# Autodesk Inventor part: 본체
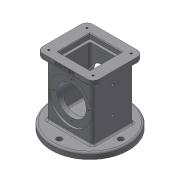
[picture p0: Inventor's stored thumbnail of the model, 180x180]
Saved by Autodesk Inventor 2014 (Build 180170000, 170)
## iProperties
Created: 2018-10
Part Number: 본체
Material: 일반
Document SubType Name: Modeling
Designer: 602-14
Density: 1 g/cm^3
Appearance: 기본값
Author: 602-14
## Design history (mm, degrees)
sketch "스케치1"
  geometry: C1 r 62.5 at (0, 0); 1 further point
  constraints: 1 centre point, 1 coincident
  dimensions: "d0" = 125 diameter of C1
extrude "돌출1" new body sketch "스케치1" distance "d1" = 10; taper "d2" = 0 deg
sketch "스케치2"
  geometry: L1 (37, -33)-(-37, -33); L2 (-37, -33)-(-37, 33); L3 (-37, 33)-(37, 33); L4 (37, 33)-(37, -33); L5 (37, -33)-(-37, 33); L6 (-37, -33)-(37, 33); 1 further point
  constraints: 12 end point, 2 midpoint, 2 parallel, 1 horizontal, 1 perpendicular
  dimensions: "d3" = 74 distance of L2.end L3.end; "d4" = 66 distance of L3.end L1.start
extrude "돌출2" join sketch "스케치2" distance "d5" = 88; taper "d6" = 0 deg
sketch "스케치3"
  geometry: L1 (46, -41)-(-46, -41); L2 (-46, -41)-(-46, 41); L3 (-46, 41)-(46, 41); L4 (46, 41)-(46, -41); L5 (46, -41)-(-46, 41); L6 (-46, -41)-(46, 41); 1 further point
  constraints: 12 end point, 2 midpoint, 2 parallel, 1 horizontal, 1 perpendicular
  dimensions: "d7" = 92 distance of L2.end L3.end; "d8" = 82 distance of L3.end L1.start
extrude "돌출3" join sketch "스케치3" distance "d9" = 10; taper "d10" = 0 deg
sketch "스케치4"
  geometry: L1 (26, -26)-(-26, -26); L2 (-26, -26)-(-26, 26); L3 (-26, 26)-(26, 26); L4 (26, 26)-(26, -26); L5 (26, -26)-(-26, 26); L6 (-26, -26)-(26, 26); 1 further point
  constraints: 12 end point, 2 midpoint, 2 parallel, 1 horizontal, 1 perpendicular
  dimensions: "d11" = 52 distance of L2.end L3.end; "d12" = 52 distance of L3.end L1.start
extrude "돌출4" cut sketch "스케치4" distance "d13" = 8; taper "d14" = 0 deg
sketch "스케치5"
  geometry: L1 (22, -22)-(-22, -22); L2 (-22, -22)-(-22, 22); L3 (-22, 22)-(22, 22); L4 (22, 22)-(22, -22); L5 (22, -22)-(-22, 22); L6 (-22, -22)-(22, 22); 1 further point
  constraints: 12 end point, 2 midpoint, 2 parallel, 1 horizontal, 1 perpendicular
  dimensions: "d15" = 44 distance of L2.end L3.end; "d16" = 44 distance of L3.end L1.start
extrude "돌출5" cut sketch "스케치5" distance "d17" = 74; taper "d18" = 0 deg
sketch "스케치6" dims "d19" = 100
  geometry: 6 further points
  constraints: 2 vertical alignment, 1 coincident, 7 other
  dimensions: "d22" = 360 deg dimension on point (0, 0) point (0, 50) (derived)
hole "구멍1" sketch "스케치6" at (0, 50), (-50, 0), (0, -50), (50, 0) diameter "d24" = 9; stored, may be unused: countersink angle "d28" = 90 deg, drill point angle "d30" = 118 deg; dims "d25" = 6, "d26" = 4, "d27" = 2, "d29" = 8
sketch "스케치7"
  geometry: L1 (98, 33)-(98, 41) reference; L2 (98, 41)-(108, 41) reference; L3 (108, 41)-(108, 26) reference; L4 (108, 26)-(100, 26) reference; L5 (100, 26)-(100, 22) reference; L6 (100, 22)-(26, 22) reference; L7 (26, 22)-(26, -22) reference; L8 (26, -22)-(100, -22) reference; L9 (100, -22)-(100, -26) reference; L10 (100, -26)-(108, -26) reference; L11 (108, -26)-(108, -41) reference; L12 (108, -41)-(98, -41) reference; L13 (98, -41)-(98, -33) reference; L14 (98, -33)-(10, -33) reference; L15 (10, -33)-(10, -45.5) reference; L16 (10, -45.5)-(0, -45.5) reference; L17 (0, -45.5)-(0, 45.5) reference; L18 (0, 45.5)-(10, 45.5) reference; L19 (10, 45.5)-(10, 33) reference; L20 (10, 33)-(98, 33) reference; L21 (10, -62.5)-(0, -62.5) reference; L22 (0, -62.5)-(0, -54.5) reference; L23 (0, -54.5)-(10, -54.5) reference; L24 (10, -54.5)-(10, -62.5) reference; L25 (0, 62.5)-(10, 62.5) reference; L26 (10, 62.5)-(10, 54.5) reference; L27 (10, 54.5)-(0, 54.5) reference; L28 (0, 54.5)-(0, 62.5) reference; L29 (89, -33)-(54, -33); L30 (54, -33)-(54, -30); L31 (54, -30)-(89, -30); L32 (89, -30)-(89, -33); L33 (54, -30)-(78, -30); L34 (78, -30)-(78, 30); L35 (78, 30)-(54, 30); L36 (54, 30)-(54, -30); L37 (54, 30)-(89, 30); L38 (89, 30)-(89, 33); L39 (89, 33)-(54, 33); L40 (54, 33)-(54, 30); 1 further point
  constraints: 24 end point, 6 parallel, 3 horizontal, 3 perpendicular, 2 point on line
  dimensions: "d31" = 54 distance from line of L17 L39.end; "d32" = 48 diameter of L34 L36; "d33" = 70 diameter of L32 L30; "d34" = 70 diameter of L38 L40; "d35" = 3 distance of L37.end L38.end; "d36" = 3 distance of L31.end L29.start; "d37" = 8 distance between parallel lines of L8 L33 (derived)
revolve "회전1" sketch "스케치7" stored, may be unused: angle "d38" = 90 deg
sketch "스케치8"
  geometry: L1 (0, 0)-(18, 0); L2 (18, 0)-(18, -28); L3 (18, -28)-(0, -28); L4 (0, -28)-(0, 0); L5 (0, -28)-(18, -24.826)
  constraints: 10 end point, 2 parallel, 1 horizontal, 1 perpendicular, 1 point on line
  dimensions: "d39" = 18 distance of L1.start L1.end; "d40" = 80 deg angle of L4 L5; "d41" = 56 diameter of L3.end L1
revolve "회전2" sketch "스케치8" stored, may be unused: angle "d42" = 90 deg
sketch "스케치9" dims "d43" = 58
  geometry: L1 (-54.829, -54)-(-54.829, -44) reference; L2 (-54.829, -44)-(-37, -44) reference; L3 (-37, -44)-(-37, 44) reference; L4 (-37, 44)-(-46, 44) reference; L5 (-46, 44)-(-46, 54) reference; L6 (-46, 54)-(46, 54) reference; L7 (46, 54)-(46, 44) reference; L8 (46, 44)-(37, 44) reference; L9 (37, 44)-(37, -44) reference; L10 (37, -44)-(54.829, -44) reference; L11 (54.829, -44)-(54.829, -54) reference; L12 (54.829, -54)-(-54.829, -54) reference; C1 r 24 at (0, 0) reference; C2 r 35 at (0, 0) reference; 6 further points
  constraints: 2 vertical alignment, 1 coincident, 7 other
  dimensions: "d46" = 360 deg dimension on C1.centre point (0, 29) (derived)
hole "구멍2" sketch "스케치9" at (0, 29), (-29, 0), (0, -29), (29, 0) diameter "d48" = 3.242; stored, may be unused: countersink angle "d52" = 90 deg, drill point angle "d54" = 120 deg; dims "d49" = 4, "d50" = 4, "d51" = 2, "d53" = 6
sketch "스케치10"
  geometry: L1 (36, -31)-(-36, -31); L2 (-36, -31)-(-36, 31); L3 (-36, 31)-(36, 31); L4 (36, 31)-(36, -31); L5 (36, -31)-(-36, 31); L6 (-36, -31)-(36, 31); 1 further point
  constraints: 12 end point, 2 midpoint, 2 parallel, 1 horizontal, 1 perpendicular
  dimensions: "d55" = 72 distance of L2.end L3.end; "d56" = 62 distance of L1.end L2.end
hole "구멍3" sketch "스케치10" at (36, 31), (36, -31), (-36, 31), (-36, -31) diameter "d57" = 3.242; stored, may be unused: countersink angle "d61" = 90 deg, drill point angle "d63" = 120 deg; dims "d58" = 4, "d59" = 4, "d60" = 2, "d62" = 6
sketch "스케치11"
  geometry: L1 (83.371, 0)-(83.371, -10) reference; L2 (83.371, -10)-(-17.371, -10) reference; L3 (-17.371, -10)-(-17.371, 0) reference; L4 (-17.371, 0)-(0, 0) reference; L5 (0, 0)-(66, 0) reference; L6 (66, 0)-(83.371, 0) reference; L7 (0, 0)-(0, 88) reference; L8 (0, 88)-(-8, 88) reference; L9 (-8, 88)-(-8, 98) reference; L10 (-8, 98)-(0.724, 98) reference; L11 (0.724, 98)-(0.724, 92) reference; L12 (3.276, 92)-(3.276, 98) reference; L13 (3.276, 98)-(62.724, 98) reference; L14 (62.724, 98)-(62.724, 92) reference; L15 (65.276, 92)-(65.276, 98) reference; L16 (65.276, 98)-(74, 98) reference; L17 (74, 98)-(74, 88) reference; L18 (74, 88)-(66, 88) reference; L19 (66, 88)-(0, 88) reference; L20 (66, 88)-(66, 0) reference; L21 (33, 98)-(33, -10); 2 further points
  constraints: 2 end point, 2 horizontal alignment, 2 point on line, 1 midpoint, 1 parallel
  dimensions: "d64" = 37 distance from line of L2 point (33, 27); "d65" = 43 distance of point (33, 27) point (33, 70)
hole "구멍4" sketch "스케치11" at (33, 27), (33, 70) diameter "d66" = 4.134; stored, may be unused: countersink angle "d70" = 90 deg, drill point angle "d72" = 120 deg; dims "d67" = 25, "d68" = 4, "d69" = 2, "d71" = 25
fillet "모깎기1" dims "d73" = 10
fillet "모깎기2" dims "d74" = 3
fillet "모깎기3" dims "d75" = 3
chamfer "모따기1" distance "d76" = 1; stored, may be unused: second distance "d77" = 2, angle "d78" = 45 deg
sketch "스케치12" dims "d37" = 8 (derived)
  geometry: L1 (1.286, 0)-(70.029, 0); L2 (70.029, 0)-(70.029, -6); L3 (70.029, -6)-(1.286, -6); L4 (1.286, -6)-(1.286, 0); L5 (72, -7)-(0, -7) reference; L6 (0, -7)-(0, 0) reference; L7 (0, 0)-(72, 0) reference; L8 (72, -7)-(72, 0) reference; L9 (-7.119, -98)-(79.119, -98) reference; L10 (83.173, -101)-(83.173, -108) reference; L11 (83.173, -108)-(-11.173, -108) reference; L12 (-11.173, -108)-(-11.173, -101) reference; L13 (1.286, 0)-(70.029, -6); L14 (70.029, 0)-(1.286, -6); 2 further points
  constraints: 4 end point, 1 collinear, 1 midpoint, 4 other
  dimensions: "d79" = 4 distance from line of L5 point (35.658, -3)
extrude "돌출6" join sketch "스케치12" distance "d80" = 0.5; taper "d81" = 0 deg
node "솔리드1"
mirror "대칭1"
node "절단 모서리 투영1"
node "절단 모서리 투영2"
node "절단 모서리 투영3"
node "절단 모서리 투영4"
